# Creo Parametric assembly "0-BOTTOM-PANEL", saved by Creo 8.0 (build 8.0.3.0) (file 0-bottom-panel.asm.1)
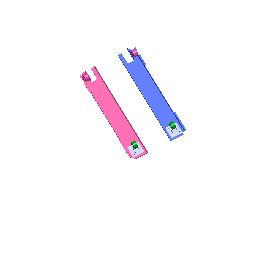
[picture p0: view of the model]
Units: millimeter Newton Second (mmNs); MM, TONNE, SECS

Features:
  1. datum plane "ADTM1"
  2. datum plane "ADTM2"
  3. datum plane "ADTM3"
  4. coordinate system
  5. component "1_BOTTOM-COVER"
  6. component "1_BOTTOM-COVER-2"
  7. component "0_CASTOR-REAR"
  8. component "0_CASTOR-REAR"
  9. component "4_CASTOR"
  10. component "4_CASTOR"

Other named items: ACS0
